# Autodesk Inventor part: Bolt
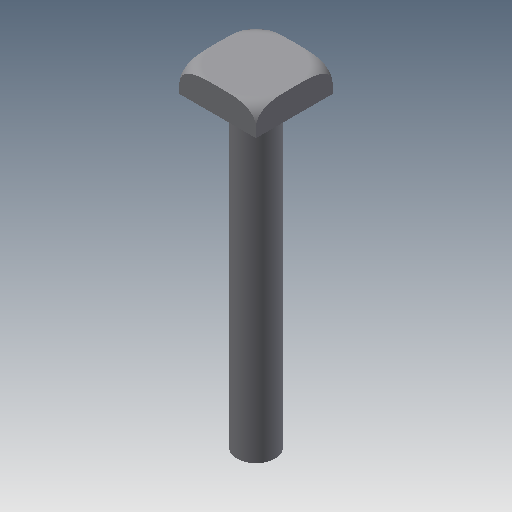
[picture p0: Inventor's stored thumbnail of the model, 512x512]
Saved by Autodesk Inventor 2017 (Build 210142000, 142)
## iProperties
Created: 2009-04
Part Number: Bolt
Document SubType Name: Modeling
Designer: Sham
Density: 1 g/cm^3
Material: Generic
Appearance: Default
Mass: 15.4123 g
Surface Area: 54.8695 cm^2
Volume: 15.4123 cm^3
Author: Sham
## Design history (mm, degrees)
sketch "Sketch1"
  geometry: L1 (-12, 12)-(12, 12); L2 (12, 12)-(12, -12); L3 (12, -12)-(-12, -12); L4 (-12, -12)-(-12, 12); 1 further point
  constraints: 8 end point, 2 parallel, 2 perpendicular, 1 horizontal, 1 other
  dimensions: "d0" = 24 distance of L1.start L1.end; "d1" = 12 distance from line of L2 point (0, 0); "d2" = 12 distance from line of L1 point (0, 0)
extrude "Extrusion1" new body sketch "Sketch1" distance "d3" = 8; taper "d4" = 0 deg
sketch "Sketch2"
  geometry: C1 r 6 at (0, 0)
  constraints: 1 centre point
  dimensions: "d5" = 12 diameter of C1
extrude "Extrusion2" join sketch "Sketch2" distance "d6" = 96; taper "d7" = 0 deg
workpoint "Work Point1"
workplane "Work Plane1"
sketch "Sketch3"
  geometry: L1 (33.941, 5)-(33.941, 6); L2 (28.941, 0)-(28.405, 0); L3 (16.971, 125.007)-(16.971, -22.043) reference; A1 r 5 centre (28.941, 5) between (28.941, 0) and (33.941, 5); 1 further point
  constraints: 4 end point, 2 point on circle, 2 point on line, 2 tangent, 1 centre point, 1 perpendicular
  dimensions: "d10" = 5 radius of A1
revolve "Revolution1" sketch "Sketch3" stored, may be unused: angle "d12" = 90 deg
body "Solid1"
other parameters: "d11" = 90 deg
